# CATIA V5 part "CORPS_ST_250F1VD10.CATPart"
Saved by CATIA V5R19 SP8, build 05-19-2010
Part number: CORPS_ST_250F1VD10
Nomenclature: 38_a
Source: Unknown
Description: NOT SPECIFIED
Bounding box of the stored display mesh (mm): x -10 to 305, y -10.5 to 10.495, z -10.5 to 10.5
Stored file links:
  C:\Users\rphgr\Desktop\0_Tapis_TC520B_vitesse\CORPS_ST_250F1VD10.CATPart
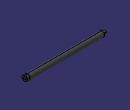
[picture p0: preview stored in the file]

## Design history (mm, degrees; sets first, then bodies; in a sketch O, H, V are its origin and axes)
AxisSystem1: origin (0, 0, 0), X (1, 0, 0), Y (0, 1, 0), Z (0, 0, 1)
Body1 "MANIFOLD_SOLID_BREP #15376" (main body)
  Solid1: solid without history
